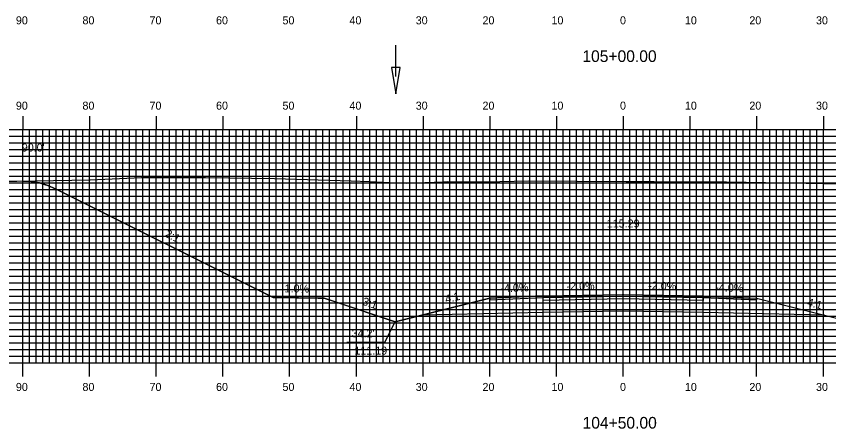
# Model space of a CAD drawing. Extents: x 1767694 to 1768037, y 442591 to 442811.
# Drawn here: x 1767768.5 to 1767890.3, y 442653.8 to 442715.7 of the extents above; entities that cross this region are included whole.
import ezdxf

# ---------------------------------------------------------------- set-up
doc = ezdxf.new("R2010")
doc.units = 0
for name, color, linetype in [('ANNOTATION', 7, 'Continuous'), ('D_Drainage_Ditch_Line', 7, 'Continuous'), ('D_Roadway_Centerline', 7, 'Continuous'), ('D_Roadway_Centerline_Text', 7, 'Continuous'), ('D_Roadway_Edge_Shoulder', 7, 'Continuous'), ('D_Roadway_Edge_TW', 7, 'Continuous'), ('D_Roadway_Pavement', 7, 'Continuous'), ('D_Roadway_SlopeLines', 7, 'Continuous'), ('D_Roadway_SubGrade', 7, 'Continuous'), ('D_Text_Standard', 7, 'Continuous'), ('H_V ANNOTATION', 7, 'Continuous'), ('MAJOR', 7, 'Continuous'), ('MINOR', 7, 'Continuous'), ('S_Roadway_Centerline', 7, 'Continuous')]:
    doc.layers.add(name, color=color, linetype=linetype)

msp = doc.modelspace()

# ---------------------------------------------------------------- linework, layer by layer
at = {"layer": 'ANNOTATION'}
msp.add_lwpolyline([(1767818.02, 442666.79), (1767823.71, 442666.79), (1767825.28, 442669.85)], dxfattribs=at)
at = {"layer": 'D_Drainage_Ditch_Line'}
msp.add_line((1767825.39, 442706.66), (1767825.39, 442711.36), dxfattribs=at)
msp.add_lwpolyline([(1767826.04, 442707.97), (1767824.73, 442707.97), (1767825.39, 442704.03)], close=True, dxfattribs=at)
at = {"layer": 'D_Roadway_Centerline'}
msp.add_lwpolyline([(1767769.45, 442690.95), (1767770.7, 442690.89), (1767771.67, 442690.72), (1767771.95, 442690.67), (1767772.5, 442690.51), (1767773.2, 442690.29), (1767773.56, 442690.13), (1767774.45, 442689.75), (1767774.46, 442689.74), (1767807, 442673.47), (1767807, 442673.47), (1767813.74, 442673.41), (1767814.65, 442673.4), (1767816.04, 442672.93), (1767825.27, 442669.85), (1767825.28, 442669.85), (1767829.28, 442670.85), (1767832.83, 442671.74), (1767839.45, 442673.4), (1767842.67, 442673.52), (1767847.45, 442673.72), (1767859.29, 442673.95), (1767859.45, 442673.96), (1767859.56, 442673.95), (1767871.45, 442673.72), (1767871.45, 442673.72), (1767876.23, 442673.52), (1767879.45, 442673.4), (1767879.45, 442673.4), (1767882.64, 442672.6), (1767889.62, 442670.85), (1767889.63, 442670.85), (1767893.62, 442669.85)], dxfattribs=at)
at = {"layer": 'D_Roadway_Edge_Shoulder'}
for points in [[(1767847.45, 442673.72), (1767839.45, 442673.4), (1767839.45, 442673.15), (1767847.45, 442673.47)], [(1767871.45, 442673.72), (1767879.45, 442673.4), (1767879.45, 442673.15), (1767871.45, 442673.47)]]:
    msp.add_lwpolyline(points, close=True, dxfattribs=at)
at = {"layer": 'D_Roadway_Edge_TW'}
msp.add_lwpolyline([(1767847.45, 442673.47), (1767847.45, 442673.72), (1767859.45, 442673.96), (1767871.45, 442673.72), (1767871.45, 442673.47), (1767859.45, 442673.71)], close=True, dxfattribs=at)
at = {"layer": 'D_Roadway_Pavement'}
msp.add_lwpolyline([(1767847.45, 442673.05), (1767847.45, 442673.47), (1767859.45, 442673.71), (1767871.45, 442673.47), (1767871.45, 442673.05), (1767859.45, 442673.29)], close=True, dxfattribs=at)
at = {"layer": 'D_Roadway_SlopeLines'}
for points in [[(1767814.65, 442673.4), (1767807, 442673.47), (1767774.45, 442689.75), (1767773.2, 442690.29), (1767771.95, 442690.67), (1767770.7, 442690.89), (1767769.45, 442690.95)], [(1767825.28, 442669.85), (1767814.65, 442673.4)], [(1767839.45, 442673.4), (1767825.28, 442669.85)], [(1767879.45, 442673.4), (1767893.62, 442669.85)]]:
    msp.add_lwpolyline(points, dxfattribs=at)
at = {"layer": 'D_Roadway_SubGrade'}
msp.add_lwpolyline([(1767847.45, 442671.22), (1767829.28, 442670.85), (1767839.45, 442673.4), (1767839.45, 442673.15), (1767847.45, 442673.47), (1767859.45, 442673.71), (1767871.45, 442673.47), (1767879.45, 442673.15), (1767879.45, 442673.4), (1767889.62, 442670.85), (1767871.45, 442671.22), (1767859.45, 442671.46)], close=True, dxfattribs=at)
at = {"layer": 'MAJOR'}
for p, q in [((1767769.45, 442700.67), (1767769.45, 442698.67)), ((1767779.45, 442700.67), (1767779.45, 442698.67)), ((1767789.45, 442700.67), (1767789.45, 442698.67)), ((1767799.45, 442700.67), (1767799.45, 442698.67)), ((1767809.45, 442700.67), (1767809.45, 442698.67)), ((1767819.45, 442700.67), (1767819.45, 442698.67)), ((1767829.45, 442700.67), (1767829.45, 442698.67)), ((1767839.45, 442700.67), (1767839.45, 442698.67)), ((1767849.45, 442700.67), (1767849.45, 442698.67)), ((1767859.45, 442700.67), (1767859.45, 442698.67)), ((1767869.45, 442700.67), (1767869.45, 442698.67)), ((1767879.45, 442700.67), (1767879.45, 442698.67)), ((1767889.45, 442700.67), (1767889.45, 442698.67)), ((1767719.45, 442698.67), (1767999.45, 442698.67)), ((1767719.45, 442698.67), (1767999.45, 442698.67)), ((1767769.45, 442663.67), (1767769.45, 442698.67)), ((1767779.45, 442663.67), (1767779.45, 442698.67)), ((1767789.45, 442663.67), (1767789.45, 442698.67)), ((1767799.45, 442663.67), (1767799.45, 442698.67)), ((1767809.45, 442663.67), (1767809.45, 442698.67)), ((1767819.45, 442663.67), (1767819.45, 442698.67)), ((1767829.45, 442663.67), (1767829.45, 442698.67)), ((1767839.45, 442663.67), (1767839.45, 442698.67)), ((1767849.45, 442663.67), (1767849.45, 442698.67)), ((1767859.45, 442663.67), (1767859.45, 442698.67)), ((1767869.45, 442663.67), (1767869.45, 442698.67)), ((1767879.45, 442663.67), (1767879.45, 442698.67)), ((1767889.45, 442663.67), (1767889.45, 442698.67)), ((1767719.45, 442693.67), (1767999.45, 442693.67)), ((1767719.45, 442688.67), (1767999.45, 442688.67)), ((1767719.45, 442683.67), (1767999.45, 442683.67)), ((1767719.45, 442678.67), (1767999.45, 442678.67)), ((1767719.45, 442673.67), (1767999.45, 442673.67)), ((1767719.45, 442668.67), (1767999.45, 442668.67)), ((1767719.45, 442663.67), (1767999.45, 442663.67)), ((1767719.45, 442663.67), (1767999.45, 442663.67)), ((1767769.45, 442661.66), (1767769.45, 442663.67)), ((1767779.45, 442661.66), (1767779.45, 442663.67)), ((1767789.45, 442661.66), (1767789.45, 442663.67)), ((1767799.45, 442661.66), (1767799.45, 442663.67)), ((1767809.45, 442661.66), (1767809.45, 442663.67)), ((1767819.45, 442661.66), (1767819.45, 442663.67)), ((1767829.45, 442661.66), (1767829.45, 442663.67)), ((1767839.45, 442661.66), (1767839.45, 442663.67)), ((1767849.45, 442661.66), (1767849.45, 442663.67)), ((1767859.45, 442661.66), (1767859.45, 442663.67)), ((1767869.45, 442661.66), (1767869.45, 442663.67)), ((1767879.45, 442661.66), (1767879.45, 442663.67)), ((1767889.45, 442661.66), (1767889.45, 442663.67))]:
    msp.add_line(p, q, dxfattribs=at)
at = {"layer": 'MINOR'}
for p, q in [((1767770.45, 442663.67), (1767770.45, 442698.67)), ((1767771.45, 442663.67), (1767771.45, 442698.67)), ((1767772.45, 442663.67), (1767772.45, 442698.67)), ((1767773.45, 442663.67), (1767773.45, 442698.67)), ((1767774.45, 442663.67), (1767774.45, 442698.67)), ((1767775.45, 442663.67), (1767775.45, 442698.67)), ((1767776.45, 442663.67), (1767776.45, 442698.67)), ((1767777.45, 442663.67), (1767777.45, 442698.67)), ((1767778.45, 442663.67), (1767778.45, 442698.67)), ((1767780.45, 442663.67), (1767780.45, 442698.67)), ((1767781.45, 442663.67), (1767781.45, 442698.67)), ((1767782.45, 442663.67), (1767782.45, 442698.67)), ((1767783.45, 442663.67), (1767783.45, 442698.67)), ((1767784.45, 442663.67), (1767784.45, 442698.67)), ((1767785.45, 442663.67), (1767785.45, 442698.67)), ((1767786.45, 442663.67), (1767786.45, 442698.67)), ((1767787.45, 442663.67), (1767787.45, 442698.67)), ((1767788.45, 442663.67), (1767788.45, 442698.67)), ((1767790.45, 442663.67), (1767790.45, 442698.67)), ((1767791.45, 442663.67), (1767791.45, 442698.67)), ((1767792.45, 442663.67), (1767792.45, 442698.67)), ((1767793.45, 442663.67), (1767793.45, 442698.67)), ((1767794.45, 442663.67), (1767794.45, 442698.67)), ((1767795.45, 442663.67), (1767795.45, 442698.67)), ((1767796.45, 442663.67), (1767796.45, 442698.67)), ((1767797.45, 442663.67), (1767797.45, 442698.67)), ((1767798.45, 442663.67), (1767798.45, 442698.67)), ((1767800.45, 442663.67), (1767800.45, 442698.67)), ((1767801.45, 442663.67), (1767801.45, 442698.67)), ((1767802.45, 442663.67), (1767802.45, 442698.67)), ((1767803.45, 442663.67), (1767803.45, 442698.67)), ((1767804.45, 442663.67), (1767804.45, 442698.67)), ((1767805.45, 442663.67), (1767805.45, 442698.67)), ((1767806.45, 442663.67), (1767806.45, 442698.67)), ((1767807.45, 442663.67), (1767807.45, 442698.67)), ((1767808.45, 442663.67), (1767808.45, 442698.67)), ((1767810.45, 442663.67), (1767810.45, 442698.67)), ((1767811.45, 442663.67), (1767811.45, 442698.67)), ((1767812.45, 442663.67), (1767812.45, 442698.67)), ((1767813.45, 442663.67), (1767813.45, 442698.67)), ((1767814.45, 442663.67), (1767814.45, 442698.67)), ((1767815.45, 442663.67), (1767815.45, 442698.67)), ((1767816.45, 442663.67), (1767816.45, 442698.67)), ((1767817.45, 442663.67), (1767817.45, 442698.67)), ((1767818.45, 442663.67), (1767818.45, 442698.67)), ((1767820.45, 442663.67), (1767820.45, 442698.67)), ((1767821.45, 442663.67), (1767821.45, 442698.67)), ((1767822.45, 442663.67), (1767822.45, 442698.67)), ((1767823.45, 442663.67), (1767823.45, 442698.67)), ((1767824.45, 442663.67), (1767824.45, 442698.67)), ((1767825.45, 442663.67), (1767825.45, 442698.67)), ((1767826.45, 442663.67), (1767826.45, 442698.67)), ((1767827.45, 442663.67), (1767827.45, 442698.67)), ((1767828.45, 442663.67), (1767828.45, 442698.67)), ((1767830.45, 442663.67), (1767830.45, 442698.67)), ((1767831.45, 442663.67), (1767831.45, 442698.67)), ((1767832.45, 442663.67), (1767832.45, 442698.67)), ((1767833.45, 442663.67), (1767833.45, 442698.67)), ((1767834.45, 442663.67), (1767834.45, 442698.67)), ((1767835.45, 442663.67), (1767835.45, 442698.67)), ((1767836.45, 442663.67), (1767836.45, 442698.67)), ((1767837.45, 442663.67), (1767837.45, 442698.67)), ((1767838.45, 442663.67), (1767838.45, 442698.67)), ((1767840.45, 442663.67), (1767840.45, 442698.67)), ((1767841.45, 442663.67), (1767841.45, 442698.67)), ((1767842.45, 442663.67), (1767842.45, 442698.67)), ((1767843.45, 442663.67), (1767843.45, 442698.67)), ((1767844.45, 442663.67), (1767844.45, 442698.67)), ((1767845.45, 442663.67), (1767845.45, 442698.67)), ((1767846.45, 442663.67), (1767846.45, 442698.67)), ((1767847.45, 442663.67), (1767847.45, 442698.67)), ((1767848.45, 442663.67), (1767848.45, 442698.67)), ((1767850.45, 442663.67), (1767850.45, 442698.67)), ((1767851.45, 442663.67), (1767851.45, 442698.67)), ((1767852.45, 442663.67), (1767852.45, 442698.67)), ((1767853.45, 442663.67), (1767853.45, 442698.67)), ((1767854.45, 442663.67), (1767854.45, 442698.67)), ((1767855.45, 442663.67), (1767855.45, 442698.67)), ((1767856.45, 442663.67), (1767856.45, 442698.67)), ((1767857.45, 442663.67), (1767857.45, 442698.67)), ((1767858.45, 442663.67), (1767858.45, 442698.67)), ((1767860.45, 442663.67), (1767860.45, 442698.67)), ((1767861.45, 442663.67), (1767861.45, 442698.67)), ((1767862.45, 442663.67), (1767862.45, 442698.67)), ((1767863.45, 442663.67), (1767863.45, 442698.67)), ((1767864.45, 442663.67), (1767864.45, 442698.67)), ((1767865.45, 442663.67), (1767865.45, 442698.67)), ((1767866.45, 442663.67), (1767866.45, 442698.67)), ((1767867.45, 442663.67), (1767867.45, 442698.67)), ((1767868.45, 442663.67), (1767868.45, 442698.67)), ((1767870.45, 442663.67), (1767870.45, 442698.67)), ((1767871.45, 442663.67), (1767871.45, 442698.67)), ((1767872.45, 442663.67), (1767872.45, 442698.67)), ((1767873.45, 442663.67), (1767873.45, 442698.67)), ((1767874.45, 442663.67), (1767874.45, 442698.67)), ((1767875.45, 442663.67), (1767875.45, 442698.67)), ((1767876.45, 442663.67), (1767876.45, 442698.67)), ((1767877.45, 442663.67), (1767877.45, 442698.67)), ((1767878.45, 442663.67), (1767878.45, 442698.67)), ((1767880.45, 442663.67), (1767880.45, 442698.67)), ((1767881.45, 442663.67), (1767881.45, 442698.67)), ((1767882.45, 442663.67), (1767882.45, 442698.67)), ((1767883.45, 442663.67), (1767883.45, 442698.67)), ((1767884.45, 442663.67), (1767884.45, 442698.67)), ((1767885.45, 442663.67), (1767885.45, 442698.67)), ((1767886.45, 442663.67), (1767886.45, 442698.67)), ((1767887.45, 442663.67), (1767887.45, 442698.67)), ((1767888.45, 442663.67), (1767888.45, 442698.67)), ((1767719.45, 442697.67), (1767999.45, 442697.67)), ((1767719.45, 442696.67), (1767999.45, 442696.67)), ((1767719.45, 442695.67), (1767999.45, 442695.67)), ((1767719.45, 442694.67), (1767999.45, 442694.67)), ((1767719.45, 442692.67), (1767999.45, 442692.67)), ((1767719.45, 442691.67), (1767999.45, 442691.67)), ((1767719.45, 442690.67), (1767999.45, 442690.67)), ((1767719.45, 442689.67), (1767999.45, 442689.67)), ((1767719.45, 442687.67), (1767999.45, 442687.67)), ((1767719.45, 442686.67), (1767999.45, 442686.67)), ((1767719.45, 442685.67), (1767999.45, 442685.67)), ((1767719.45, 442684.67), (1767999.45, 442684.67)), ((1767719.45, 442682.67), (1767999.45, 442682.67)), ((1767719.45, 442681.67), (1767999.45, 442681.67)), ((1767719.45, 442680.67), (1767999.45, 442680.67)), ((1767719.45, 442679.67), (1767999.45, 442679.67)), ((1767719.45, 442677.67), (1767999.45, 442677.67)), ((1767719.45, 442676.67), (1767999.45, 442676.67)), ((1767719.45, 442675.67), (1767999.45, 442675.67)), ((1767719.45, 442674.67), (1767999.45, 442674.67)), ((1767719.45, 442672.67), (1767999.45, 442672.67)), ((1767719.45, 442671.67), (1767999.45, 442671.67)), ((1767719.45, 442670.67), (1767999.45, 442670.67)), ((1767719.45, 442669.67), (1767999.45, 442669.67)), ((1767719.45, 442667.67), (1767999.45, 442667.67)), ((1767719.45, 442666.67), (1767999.45, 442666.67)), ((1767719.45, 442665.67), (1767999.45, 442665.67)), ((1767719.45, 442664.67), (1767999.45, 442664.67))]:
    msp.add_line(p, q, dxfattribs=at)
at = {"layer": 'S_Roadway_Centerline'}
msp.add_lwpolyline([(1767765.88, 442690.93), (1767768.54, 442690.94), (1767779.54, 442691.13), (1767787.27, 442691.5), (1767796.83, 442691.5), (1767807.19, 442691.32), (1767818.65, 442690.97), (1767821.43, 442690.88), (1767825.46, 442690.71), (1767826.93, 442690.66), (1767832.5, 442690.86), (1767833.04, 442690.87), (1767833.69, 442690.84), (1767838.84, 442690.83), (1767845.2, 442690.97), (1767859.88, 442690.89), (1767862.38, 442690.89), (1767864.11, 442690.89), (1767874.92, 442690.84), (1767883.72, 442690.68), (1767886.88, 442690.66), (1767891.9, 442690.55)], dxfattribs=at)

# ---------------------------------------------------------------- texts
at = {"layer": 'ANNOTATION'}
for s, rotation, p in [('2:1', 333.435, (1767790.66, 442682.68)), ('1.0%', 359.4306, (1767808.7, 442674.26)), ('-4.0%', 2.2909, (1767841.08, 442674.26)), ('-2.0%', 1.1458, (1767850.98, 442674.59)), ('-2.0%', 358.8543, (1767863.19, 442674.68)), ('-4.0%', 357.7092, (1767873.24, 442674.45)), ('4:1', 14.0377, (1767832.9, 442672.62)), ('3:1', 341.5622, (1767820.26, 442672.43)), ('4:1', 345.9616, (1767886.94, 442672.25))]:
    msp.add_text(s, height=1.2, rotation=rotation, dxfattribs=at).set_placement(p)
for s, p in [("34.2'", (1767818.75, 442667.52)), ('111.19', (1767819.16, 442664.92))]:
    msp.add_text(s, height=1.2, dxfattribs=at).set_placement(p)
at = {"layer": 'D_Roadway_Centerline'}
for s, p in [('C', (1767859.44, 442673.96)), ('L', (1767859.45, 442673.95))]:
    msp.add_text(s, height=0.0146, dxfattribs=at).set_placement(p)
at = {"layer": 'D_Roadway_Centerline_Text'}
msp.add_text('115.29', height=1.2, dxfattribs=at).set_placement((1767856.99, 442683.99))
at = {"layer": 'D_Text_Standard'}
msp.add_text("90.0'", height=1.2, dxfattribs=at).set_placement((1767769.31, 442695.39))
at = {"layer": 'H_V ANNOTATION'}
for s, height, p in [('90', 1.2, (1767768.42, 442714.47)), ('80', 1.2, (1767778.4, 442714.47)), ('70', 1.2, (1767788.45, 442714.47)), ('60', 1.2, (1767798.42, 442714.47)), ('50', 1.2, (1767808.38, 442714.47)), ('40', 1.2, (1767818.42, 442714.47)), ('30', 1.2, (1767828.35, 442714.47)), ('20', 1.2, (1767838.36, 442714.47)), ('10', 1.2, (1767848.7, 442714.47)), ('0', 1.2, (1767858.97, 442714.47)), ('10', 1.2, (1767868.7, 442714.47)), ('20', 1.2, (1767878.36, 442714.47)), ('30', 1.2, (1767888.35, 442714.47)), ('105+00.00', 1.75, (1767853.33, 442708.82)), ('90', 1.2, (1767768.42, 442701.67)), ('80', 1.2, (1767778.4, 442701.67)), ('70', 1.2, (1767788.45, 442701.67)), ('60', 1.2, (1767798.42, 442701.67)), ('50', 1.2, (1767808.38, 442701.67)), ('40', 1.2, (1767818.42, 442701.67)), ('30', 1.2, (1767828.35, 442701.67)), ('20', 1.2, (1767838.36, 442701.67)), ('10', 1.2, (1767848.7, 442701.67)), ('0', 1.2, (1767858.97, 442701.67)), ('10', 1.2, (1767868.7, 442701.67)), ('20', 1.2, (1767878.36, 442701.67)), ('30', 1.2, (1767888.35, 442701.67)), ('90', 1.2, (1767768.42, 442659.47)), ('80', 1.2, (1767778.4, 442659.47)), ('70', 1.2, (1767788.45, 442659.47)), ('60', 1.2, (1767798.42, 442659.47)), ('50', 1.2, (1767808.38, 442659.47)), ('40', 1.2, (1767818.42, 442659.47)), ('30', 1.2, (1767828.35, 442659.47)), ('20', 1.2, (1767838.36, 442659.47)), ('10', 1.2, (1767848.7, 442659.47)), ('0', 1.2, (1767858.97, 442659.47)), ('10', 1.2, (1767868.7, 442659.47)), ('20', 1.2, (1767878.36, 442659.47)), ('30', 1.2, (1767888.35, 442659.47)), ('104+50.00', 1.75, (1767853.36, 442653.82))]:
    msp.add_text(s, height=height, dxfattribs=at).set_placement(p)

doc.saveas('drawing.dxf')
